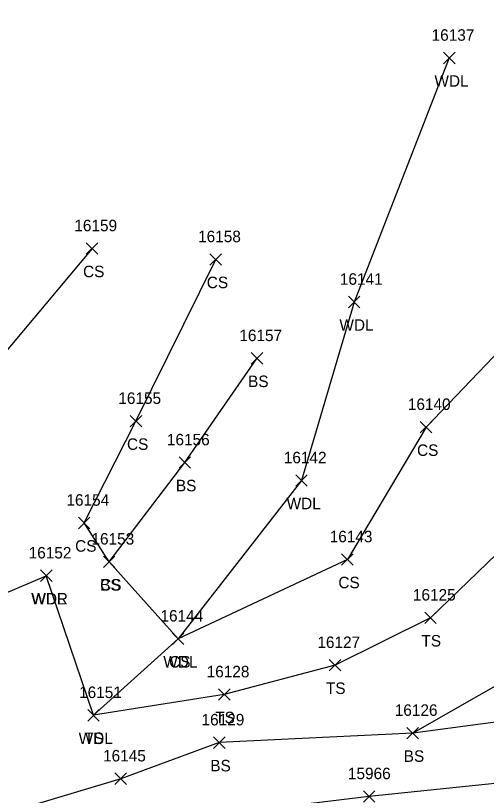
# Model space of a CAD drawing. Extents: x 1606530 to 1613020, y 784959 to 789666.
# Drawn here: x 1609171.7 to 1609253.6, y 788467.6 to 788603.3 of the extents above; entities that cross this region are included whole.
import ezdxf

# ---------------------------------------------------------------- set-up
doc = ezdxf.new("R2010")
doc.units = 0
for name, color, linetype in [('L_A', 7, 'Continuous'), ('L_I', 7, 'Continuous'), ('L_TIC', 7, 'Continuous'), ('LAWA', 7, 'Continuous'), ('LELB', 7, 'Continuous')]:
    doc.layers.add(name, color=color, linetype=linetype)

msp = doc.modelspace()

# ---------------------------------------------------------------- linework, layer by layer
at = {"layer": 'L_TIC'}
for points in [[(1609246.14, 788594.89), (1609248.14, 788596.89)], [(1609248.14, 788594.89), (1609246.14, 788596.89)], [(1609184.03, 788561.74), (1609186.03, 788563.74)], [(1609186.03, 788561.74), (1609184.03, 788563.74)], [(1609205.54, 788559.83), (1609207.54, 788561.83)], [(1609207.54, 788559.83), (1609205.54, 788561.83)], [(1609229.62, 788552.42), (1609231.62, 788554.42)], [(1609231.62, 788552.42), (1609229.62, 788554.42)], [(1609212.71, 788542.62), (1609214.71, 788544.62)], [(1609214.71, 788542.62), (1609212.71, 788544.62)], [(1609191.67, 788531.69), (1609193.67, 788533.69)], [(1609193.67, 788531.69), (1609191.67, 788533.69)], [(1609242.1, 788530.64), (1609244.1, 788532.64)], [(1609244.1, 788530.64), (1609242.1, 788532.64)], [(1609200.17, 788524.48), (1609202.17, 788526.48)], [(1609202.17, 788524.48), (1609200.17, 788526.48)], [(1609220.44, 788521.36), (1609222.44, 788523.36)], [(1609222.44, 788521.36), (1609220.44, 788523.36)], [(1609182.65, 788513.97), (1609184.65, 788515.97)], [(1609184.65, 788513.97), (1609182.65, 788515.97)], [(1609187, 788507.21), (1609189, 788509.21)], [(1609189, 788507.21), (1609187, 788509.21)], [(1609187, 788507.21), (1609189, 788509.21)], [(1609189, 788507.21), (1609187, 788509.21)], [(1609228.42, 788507.61), (1609230.42, 788509.61)], [(1609230.42, 788507.61), (1609228.42, 788509.61)], [(1609176.08, 788504.79), (1609178.08, 788506.79)], [(1609178.08, 788504.79), (1609176.08, 788506.79)], [(1609176.08, 788504.79), (1609178.08, 788506.79)], [(1609178.08, 788504.79), (1609176.08, 788506.79)], [(1609242.89, 788497.47), (1609244.89, 788499.47)], [(1609244.89, 788497.47), (1609242.89, 788499.47)], [(1609199, 788493.81), (1609201, 788495.81)], [(1609201, 788493.81), (1609199, 788495.81)], [(1609199, 788493.81), (1609201, 788495.81)], [(1609201, 788493.81), (1609199, 788495.81)], [(1609226.28, 788489.21), (1609228.28, 788491.21)], [(1609228.28, 788489.21), (1609226.28, 788491.21)], [(1609207.03, 788484.11), (1609209.03, 788486.11)], [(1609209.03, 788484.11), (1609207.03, 788486.11)], [(1609184.28, 788480.5), (1609186.28, 788482.5)], [(1609186.28, 788480.5), (1609184.28, 788482.5)], [(1609184.28, 788480.5), (1609186.28, 788482.5)], [(1609186.28, 788480.5), (1609184.28, 788482.5)], [(1609239.78, 788477.4), (1609241.78, 788479.4)], [(1609241.78, 788477.4), (1609239.78, 788479.4)], [(1609239.78, 788477.4), (1609241.78, 788479.4)], [(1609241.78, 788477.4), (1609239.78, 788479.4)], [(1609206.15, 788475.74), (1609208.15, 788477.74)], [(1609208.15, 788475.74), (1609206.15, 788477.74)], [(1609189.02, 788469.47), (1609191.02, 788471.47)], [(1609191.02, 788469.47), (1609189.02, 788471.47)], [(1609232.21, 788466.38), (1609234.21, 788468.38)], [(1609234.21, 788466.38), (1609232.21, 788468.38)]]:
    msp.add_lwpolyline(points, dxfattribs=at)
at = {"layer": 'LAWA'}
for points in [[(1609247.14, 788595.89), (1609230.62, 788553.42), (1609221.44, 788522.36), (1609200, 788494.81), (1609185.28, 788481.5), (1609177.08, 788505.79)], [(1609458.89, 788516.22), (1609465.52, 788489.74), (1609475.82, 788469.82), (1609458.93, 788473.78), (1609440.54, 788476.41), (1609422.32, 788472.18), (1609400.86, 788472.53), (1609378.74, 788469.08), (1609331.76, 788471.95), (1609305.7, 788472.62), (1609293.07, 788472.82), (1609275.81, 788471.77), (1609233.21, 788467.38), (1609185.7, 788461.65), (1609159.09, 788461.18), (1609160.3, 788482.23), (1609154.12, 788496.01), (1609177.08, 788505.79)]]:
    msp.add_lwpolyline(points, dxfattribs=at)
at = {"layer": 'LELB'}
for points in [[(1609319.77, 788603.27), (1609301.37, 788576.74), (1609263.88, 788553.33), (1609243.1, 788531.64), (1609229.42, 788508.61), (1609200, 788494.81), (1609188, 788508.21), (1609183.65, 788514.97), (1609192.67, 788532.69), (1609206.54, 788560.83)], [(1609185.03, 788562.74), (1609165, 788538.82), (1609151.78, 788518.23)], [(1609305.24, 788558.08), (1609292.12, 788546.53), (1609272.3, 788525.77), (1609258.63, 788512.74), (1609243.89, 788498.47), (1609227.28, 788490.21), (1609208.03, 788485.11), (1609185.28, 788481.5)], [(1609188, 788508.21), (1609201.17, 788525.48), (1609213.71, 788543.62)], [(1609305.81, 788532.99), (1609293.73, 788522.09), (1609276.76, 788509.53), (1609263.73, 788491.49), (1609240.78, 788478.4)], [(1609288.12, 788482.43), (1609278.7, 788483.44), (1609240.78, 788478.4), (1609207.15, 788476.74), (1609190.02, 788470.47), (1609159.09, 788461.18)]]:
    msp.add_lwpolyline(points, dxfattribs=at)

# ---------------------------------------------------------------- texts
at = {"layer": 'L_A'}
for s, p in [('WDL', (1609244.56, 788590.89)), ('CS', (1609183.47, 788557.74)), ('CS', (1609204.98, 788555.83)), ('WDL', (1609228.04, 788548.42)), ('BS', (1609212.16, 788538.62)), ('CS', (1609191.11, 788527.69)), ('CS', (1609241.54, 788526.64)), ('BS', (1609199.61, 788520.48)), ('WDL', (1609218.86, 788517.36)), ('CS', (1609182.09, 788509.97)), ('CS', (1609186.44, 788503.21)), ('BS', (1609186.44, 788503.21)), ('CS', (1609227.86, 788503.61)), ('WDR', (1609174.44, 788500.79)), ('WDL', (1609174.5, 788500.79)), ('TS', (1609242.3, 788493.47)), ('WDL', (1609197.42, 788489.81)), ('CS', (1609198.44, 788489.81)), ('TS', (1609225.69, 788485.21)), ('TS', (1609206.44, 788480.11)), ('WDL', (1609182.7, 788476.5)), ('TS', (1609183.69, 788476.5)), ('BS', (1609239.22, 788473.4)), ('BS', (1609239.22, 788473.4)), ('BS', (1609205.59, 788471.74))]:
    msp.add_text(s, height=2, dxfattribs=at).set_placement(p)
at = {"layer": 'L_I'}
for s, p in [('16137', (1609244.07, 788598.89)), ('16159', (1609181.95, 788565.74)), ('16158', (1609203.47, 788563.83)), ('16141', (1609228.12, 788556.42)), ('16157', (1609210.64, 788546.62)), ('16155', (1609189.6, 788535.69)), ('16140', (1609239.94, 788534.64)), ('16156', (1609198.05, 788528.48)), ('16142', (1609218.37, 788525.36)), ('16154', (1609180.58, 788517.97)), ('16153', (1609184.93, 788511.21)), ('16153', (1609184.93, 788511.21)), ('16143', (1609226.35, 788511.61)), ('16152', (1609174.01, 788508.79)), ('16152', (1609174.01, 788508.79)), ('16125', (1609240.82, 788501.47)), ('16144', (1609196.93, 788497.81)), ('16144', (1609196.93, 788497.81)), ('16127', (1609224.21, 788493.21)), ('16128', (1609204.96, 788488.11)), ('16151', (1609182.78, 788484.5)), ('16151', (1609182.78, 788484.5)), ('16126', (1609237.66, 788481.4)), ('16126', (1609237.66, 788481.4)), ('16129', (1609204.07, 788479.74)), ('16145', (1609186.95, 788473.47)), ('15966', (1609229.52, 788470.38))]:
    msp.add_text(s, height=2, dxfattribs=at).set_placement(p)

doc.saveas('drawing.dxf')
